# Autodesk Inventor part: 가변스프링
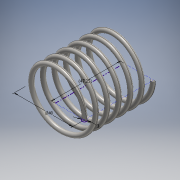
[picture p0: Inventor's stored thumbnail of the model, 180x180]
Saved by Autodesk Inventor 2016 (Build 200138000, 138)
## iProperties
Created: 2018-02
Part Number: 가변스프링
Material: 스테인레스 스틸
Document SubType Name: Modeling
Designer: 605-04
Density: 8 g/cm^3
Appearance: 반연마
Mass: 42.0618 g
Surface Area: 70.8915 cm^2
Volume: 5.25773 cm^3
Author: 605-04
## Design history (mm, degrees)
sketch "스케치1"
  geometry: L1 (0, 0)-(0, 47.25); L2 (0, 47.25)-(20, 47.25); L3 (20, 47.25)-(20, 0); L4 (20, 0)-(0, 0); C1 r 1.5 at (20, 0)
  constraints: 8 end point, 3 perpendicular, 1 centre point, 1 coincident, 1 vertical
  dimensions: "d0" = 47.25 distance of L1.start L1.end (derived); "d1" = 40 diameter of L3 L1; "d2" = 3 diameter of C1
feature "코일1" sketch "스케치1" pitch "d3" = 10; turns "d5" = 6; dims "d4" = 47.25 (= d0), "d6" = 0, angle "d7" = 90 deg, angle "d8" = 90 deg, "d9" = 0, "d10" = 0
sketch "스케치2"
  geometry: L1 (-18.5, 0)-(-21.5, 0) reference; L2 (-18.5, 0)-(-21.5, 0) reference; 1 further point
  constraints: 2 horizontal alignment
extrude "돌출1" cut sketch "스케치2" distance "d11" = 10; taper "d12" = 0 deg
node "작업 평면1"
sketch "스케치3"
  geometry: L1 (18.5, 0)-(21.5, 0) reference; 1 further point
  constraints: 1 horizontal alignment
extrude "돌출2" cut sketch "스케치3" distance "d14" = 10; taper "d15" = 0 deg
node "솔리드1"
node "절단 모서리 투영1"
node "절단 모서리 투영2"
node "절단 모서리 투영3"
other parameters: "d13" = 90 deg
